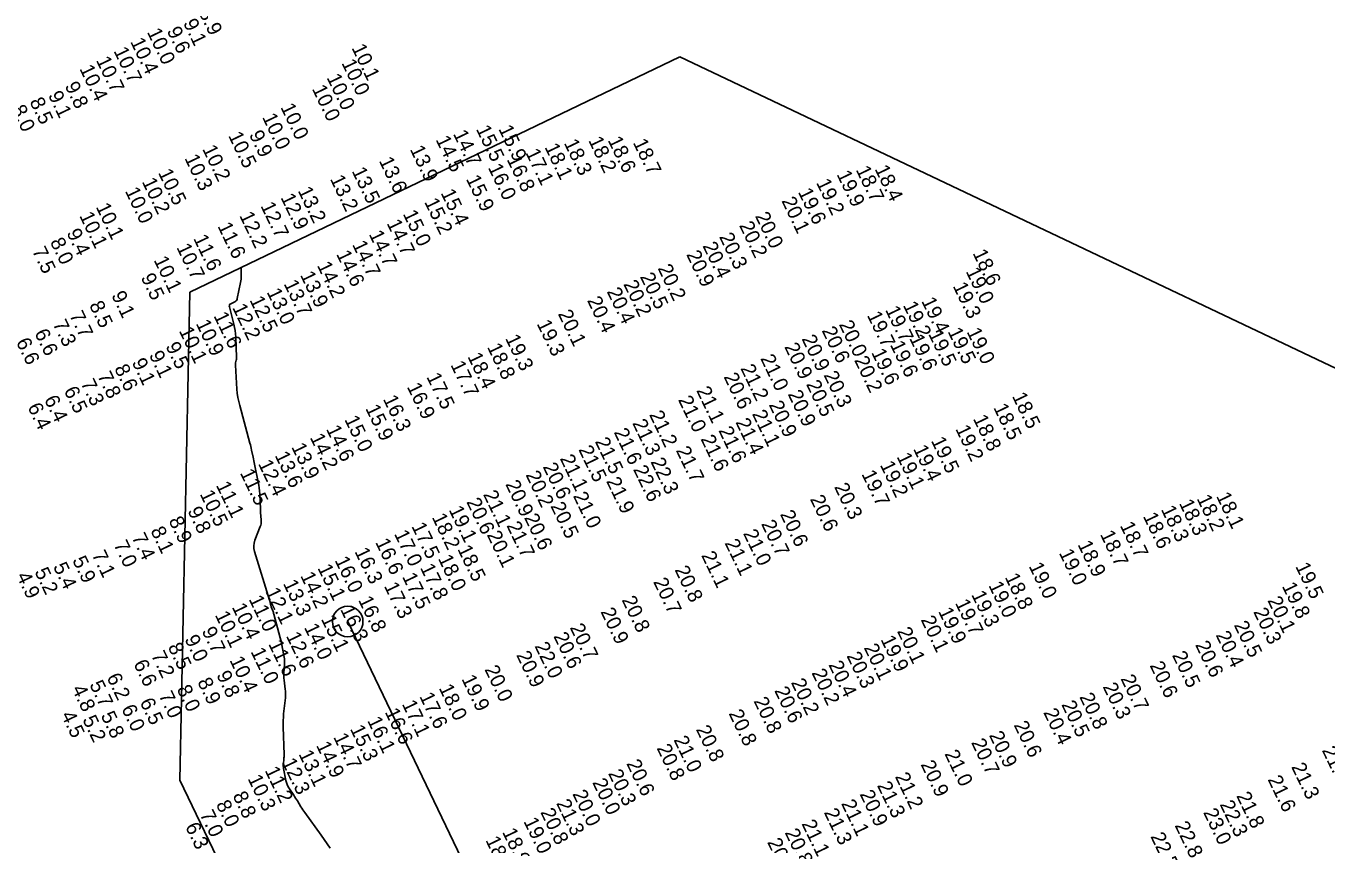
# Model space of a CAD drawing. Extents: x 507575 to 511975, y 1309304 to 1312704.
# Drawn here: x 508170 to 509066, y 1310994 to 1311558 of the extents above; entities that cross this region are included whole.
import ezdxf

# ---------------------------------------------------------------- set-up
doc = ezdxf.new("R2010")
doc.units = 0
for name, color, linetype in [('C-CHAN-CNTR', 7, 'Continuous'), ('C-CHAN-TBAS', 7, 'Continuous'), ('V-CHAN-CNTR-IDEN', 7, 'Continuous'), ('V-TOPO-MAJR', 7, 'Continuous'), ('V-TOPO-SOUN', 7, 'Continuous')]:
    doc.layers.add(name, color=color, linetype=linetype)

msp = doc.modelspace()

# ---------------------------------------------------------------- linework, layer by layer
at = {"layer": 'C-CHAN-CNTR'}
msp.add_line((508990.23, 1309901.57), (508391.7, 1311148.18), dxfattribs=at)
at = {"layer": 'C-CHAN-TBAS'}
for p, q in [((508620.36, 1311537.08), (508283.12, 1311375.16)), ((508620.36, 1311537.08), (509259.42, 1311233.71)), ((508276.04, 1311039.02), (508283.12, 1311375.16)), ((508276.04, 1311039.02), (508487, 1310599.65))]:
    msp.add_line(p, q, dxfattribs=at)
at = {"layer": 'V-CHAN-CNTR-IDEN'}
msp.add_circle((508391.7, 1311148.18), 10.54, dxfattribs=at)
at = {"layer": 'V-TOPO-MAJR'}
msp.add_lwpolyline([(508318.31, 1311392.06), (508318.32, 1311391.23), (508318.39, 1311386.42), (508318.37, 1311385.23), (508318.29, 1311384.03), (508318.15, 1311382.85), (508317.94, 1311381.67), (508315.71, 1311370.73), (508315.49, 1311370.01), (508315.13, 1311369.41), (508314.64, 1311368.9), (508314.01, 1311368.5), (508311.22, 1311367.1), (508310.64, 1311366.7), (508310.28, 1311366.2), (508310.14, 1311365.6), (508310.23, 1311364.89), (508313.33, 1311353.05), (508313.85, 1311350.82), (508314.25, 1311348.56), (508314.52, 1311346.29), (508314.67, 1311344), (508315.17, 1311330.02), (508315.17, 1311329.57), (508315.14, 1311329.12), (508315.08, 1311328.68), (508314.98, 1311328.23), (508314.54, 1311326.48), (508314.45, 1311326.04), (508314.39, 1311325.59), (508314.37, 1311325.15), (508314.38, 1311324.7), (508315.45, 1311308.31), (508315.71, 1311305.44), (508316.11, 1311302.6), (508316.66, 1311299.78), (508317.35, 1311296.98), (508324.43, 1311271.14), (508324.75, 1311269.94), (508325.04, 1311268.72), (508325.32, 1311267.51), (508325.57, 1311266.28), (508326.54, 1311261.38), (508326.78, 1311260.16), (508327.03, 1311258.93), (508327.28, 1311257.71), (508327.53, 1311256.49), (508330.09, 1311244.27), (508330.48, 1311242.23), (508330.78, 1311240.18), (508331, 1311238.12), (508331.13, 1311236.04), (508331.61, 1311225.59), (508331.66, 1311224.58), (508331.71, 1311223.57), (508331.77, 1311222.56), (508331.84, 1311221.55), (508332.11, 1311217.52), (508332.13, 1311216.52), (508332.03, 1311215.54), (508331.83, 1311214.57), (508331.52, 1311213.62), (508327.86, 1311204.18), (508327.3, 1311202.29), (508327.06, 1311200.38), (508327.16, 1311198.46), (508327.59, 1311196.54), (508337.96, 1311162.98), (508338.07, 1311162.6), (508338.17, 1311162.21), (508338.26, 1311161.83), (508338.34, 1311161.44), (508338.63, 1311159.88), (508338.71, 1311159.49), (508338.81, 1311159.11), (508338.92, 1311158.73), (508339.06, 1311158.36), (508340.11, 1311155.6), (508340.32, 1311155.01), (508340.52, 1311154.42), (508340.71, 1311153.82), (508340.88, 1311153.22), (508345.25, 1311137.03), (508345.66, 1311135.45), (508346.03, 1311133.87), (508346.38, 1311132.29), (508346.68, 1311130.69), (508347.96, 1311123.73), (508348.16, 1311122.41), (508348.27, 1311121.09), (508348.29, 1311119.76), (508348.23, 1311118.43), (508347.8, 1311113.1), (508347.73, 1311111.76), (508347.73, 1311110.43), (508347.8, 1311109.1), (508347.94, 1311107.77), (508348.76, 1311101.62), (508348.91, 1311100.15), (508348.97, 1311098.68), (508348.94, 1311097.21), (508348.83, 1311095.74), (508347.62, 1311084.69), (508347.41, 1311082.36), (508347.28, 1311080.02), (508347.23, 1311077.68), (508347.27, 1311075.34), (508347.88, 1311056.69), (508347.9, 1311055.88), (508347.88, 1311055.06), (508347.83, 1311054.25), (508347.76, 1311053.44), (508347.4, 1311050.19), (508347.34, 1311049.38), (508347.34, 1311048.57), (508347.4, 1311047.77), (508347.53, 1311046.97), (508349.15, 1311038.69), (508349.48, 1311037.34), (508349.93, 1311036.05), (508350.51, 1311034.81), (508351.22, 1311033.61), (508354.53, 1311028.59), (508355.18, 1311027.6), (508355.82, 1311026.61), (508356.45, 1311025.61), (508357.07, 1311024.61), (508359.54, 1311020.59), (508360.17, 1311019.59), (508360.82, 1311018.6), (508361.48, 1311017.63), (508362.17, 1311016.67), (508373.5, 1311001.03), (508375.6, 1310998.09), (508377.66, 1310995.12), (508379.68, 1310992.13)], dxfattribs=at)

# ---------------------------------------------------------------- texts
at = {"layer": 'V-TOPO-SOUN'}
for s, p in [('8.9', (508288.92, 1311567.85)), ('9.6', (508266.96, 1311555.2)), ('9.1', (508278.2, 1311560.62)), ('10.4 ', (508241.79, 1311547.67)), ('10.0 ', (508253.31, 1311554.29)), ('10.7 ', (508230.31, 1311541.32)), ('10.1 ', (508394.19, 1311543.41)), ('10.4 ', (508206.81, 1311529.04)), ('10.7 ', (508218.21, 1311534.86)), ('10.0 ', (508387.24, 1311532.97)), ('10.0 ', (508377.03, 1311522.89)), ('9.1', (508185.24, 1311510.88)), ('9.8', (508196.66, 1311517.27)), ('10.0 ', (508366.94, 1311515.2)), ('8.0', (508159.98, 1311501.27)), ('8.5', (508172.44, 1311506.42)), ('10.0 ', (508345.21, 1311502.56)), ('10.0 ', (508332.61, 1311495.68)), ('9.9', (508323.57, 1311483.73)), ('14.7 ', (508464.08, 1311484.19)), ('15.5 ', (508479.88, 1311487.44)), ('15.9 ', (508495.32, 1311487.59)), ('10.5 ', (508309.23, 1311482.98)), ('14.5 ', (508452.11, 1311480.2)), ('18.1 ', (508527.09, 1311475.03)), ('18.3 ', (508540.38, 1311477.92)), ('18.2 ', (508557.23, 1311479.66)), ('18.6 ', (508570.62, 1311479.77)), ('18.7 ', (508587.94, 1311478.11)), ('10.3 ', (508279.12, 1311467.44)), ('10.2 ', (508291.37, 1311473.81)), ('13.9 ', (508434.34, 1311473.56)), ('16.8 ', (508501.02, 1311466.59)), ('17.1 ', (508513.94, 1311471.27)), ('10.5 ', (508260.94, 1311457.42)), ('13.5 ', (508394.3, 1311458.59)), ('13.6 ', (508413.03, 1311465.62)), ('16.0 ', (508488.14, 1311460.91)), ('18.7 ', (508741.42, 1311459.46)), ('18.4 ', (508754.41, 1311459.99)), ('10.2 ', (508249.8, 1311451.24)), ('13.2 ', (508379.34, 1311453.17)), ('15.9 ', (508472.99, 1311453.1)), ('19.2 ', (508714.14, 1311450.53)), ('19.9 ', (508728.19, 1311456.28)), ('10.0 ', (508238.16, 1311444.77)), ('12.9 ', (508345.27, 1311440.41)), ('13.2 ', (508357.15, 1311445.08)), ('15.4 ', (508455.55, 1311443.47)), ('19.6 ', (508701.61, 1311444.14)), ('10.1 ', (508218.08, 1311433.87)), ('12.7 ', (508331.47, 1311434.6)), ('15.2 ', (508444.28, 1311437.25)), ('20.1 ', (508690.27, 1311438.03)), ('10.1 ', (508206.72, 1311427.76)), ('12.2 ', (508316.9, 1311427.88)), ('14.7 ', (508418.35, 1311422.61)), ('15.0 ', (508429.49, 1311429.06)), ('20.2 ', (508661.08, 1311421.15)), ('20.0 ', (508672.02, 1311427.61)), ('9.4', (508197.94, 1311416.03)), ('11.6 ', (508301.87, 1311420.6)), ('14.7 ', (508406.08, 1311415.05)), ('20.3 ', (508647.32, 1311413.29)), ('7.5', (508174.15, 1311403.6)), ('8.0', (508186.53, 1311409.83)), ('10.7 ', (508273.59, 1311405.99)), ('11.6 ', (508285.2, 1311412.16)), ('14.7 ', (508394.6, 1311407.97)), ('20.4 ', (508635.9, 1311407.02)), ('10.1 ', (508257.93, 1311397.28)), ('14.6 ', (508383.64, 1311401.32)), ('20.9 ', (508624.66, 1311401.12)), ('18.6 ', (508821.86, 1311402.01)), ('9.5', (508249.03, 1311385.3)), ('13.9 ', (508358.77, 1311386.91)), ('14.2 ', (508370.4, 1311393.52)), ('20.5 ', (508592.8, 1311385.82)), ('20.2 ', (508604.98, 1311391.6)), ('19.0 ', (508817.12, 1311389.46)), ('13.7 ', (508347.47, 1311380.9)), ('20.2 ', (508581.38, 1311380.67)), ('19.3 ', (508808.2, 1311379.33)), ('9.1', (508228.76, 1311373.05)), ('12.5 ', (508323.93, 1311369.76)), ('13.0 ', (508335.74, 1311375.18)), ('20.4 ', (508556.38, 1311369.44)), ('20.4 ', (508569.94, 1311375.56)), ('19.4 ', (508786.56, 1311369)), ('7.7', (508199.89, 1311359.27)), ('8.5', (508213.49, 1311366.23)), ('11.6 ', (508299.15, 1311358.83)), ('12.2 ', (508312.06, 1311364.48)), ('20.1 ', (508536.27, 1311360.24)), ('19.7 ', (508749.1, 1311359.25)), ('19.7 ', (508761.65, 1311362.97)), ('19.2 ', (508773.91, 1311366.08)), ('7.3', (508188.39, 1311353.34)), ('10.9 ', (508286.95, 1311353.53)), ('19.3 ', (508521.67, 1311353.42)), ('20.0 ', (508729.81, 1311352.96)), ('6.6', (508163.13, 1311340.82)), ('6.6', (508175.79, 1311346.99)), ('10.1 ', (508275.29, 1311348.55)), ('19.3 ', (508499.99, 1311343.33)), ('20.9 ', (508704.11, 1311342.99)), ('20.6 ', (508717.97, 1311348.69)), ('19.6 ', (508778.23, 1311343.38)), ('19.5 ', (508791.3, 1311346.41)), ('19.5 ', (508804.65, 1311348.05)), ('19.0 ', (508817.72, 1311347.91)), ('9.1', (508254.7, 1311331.93)), ('9.5', (508266.09, 1311337.96)), ('18.8 ', (508487.51, 1311337.31)), ('20.9 ', (508692.19, 1311337.52)), ('19.6 ', (508752.07, 1311333.58)), ('19.6 ', (508764.98, 1311338.91)), ('8.6', (508230.78, 1311322.63)), ('9.1', (508242.89, 1311326.84)), ('17.7 ', (508462.31, 1311325.11)), ('18.4 ', (508473.99, 1311330.83)), ('21.2 ', (508661.98, 1311322.69)), ('21.0 ', (508675.67, 1311329.49)), ('20.2 ', (508740.33, 1311328.3)), ('7.8', (508219.16, 1311317.57)), ('17.5 ', (508445.72, 1311316.84)), ('20.6 ', (508650.4, 1311316.86)), ('20.3 ', (508719.26, 1311318.07)), ('6.5', (508196.06, 1311307.39)), ('7.3', (508207.64, 1311312.45)), ('16.9 ', (508432.28, 1311309.99)), ('21.1 ', (508631.58, 1311307.4)), ('20.9 ', (508694.57, 1311304.9)), ('20.5 ', (508707.19, 1311311.75)), ('6.4', (508171.05, 1311296.02)), ('6.4', (508182.48, 1311301.25)), ('16.3 ', (508415.8, 1311301.52)), ('21.0 ', (508619.04, 1311301)), ('20.9 ', (508681.5, 1311297.6)), ('18.5 ', (508848.99, 1311303.48)), ('15.0 ', (508389.26, 1311287.46)), ('15.9 ', (508403.69, 1311295.1)), ('21.2 ', (508599.13, 1311290.79)), ('21.1 ', (508669.97, 1311291.27)), ('18.8 ', (508822.12, 1311288)), ('18.5 ', (508836.12, 1311295.69)), ('14.6 ', (508376.64, 1311280.82)), ('21.6 ', (508574.79, 1311278.65)), ('21.3 ', (508587.54, 1311284.89)), ('21.6 ', (508646.85, 1311279.87)), ('21.4 ', (508658.57, 1311285.54)), ('19.2 ', (508809.99, 1311280.93)), ('14.2 ', (508365.47, 1311275.08)), ('21.5 ', (508561.77, 1311272.28)), ('21.6 ', (508634.54, 1311274.05)), ('19.5 ', (508793.19, 1311272.81)), ('13.6 ', (508341.26, 1311262.75)), ('13.9 ', (508352.68, 1311268.59)), ('21.1 ', (508537.66, 1311260.51)), ('21.5 ', (508550.43, 1311266.74)), ('21.7 ', (508617.51, 1311266.2)), ('19.1 ', (508769.53, 1311261.82)), ('19.4 ', (508780.91, 1311267.2)), ('12.4 ', (508329.82, 1311256.98)), ('20.6 ', (508525.84, 1311254.9)), ('22.6 ', (508588.07, 1311253.12)), ('22.3 ', (508600.07, 1311258.34)), ('19.2 ', (508758.06, 1311256.13)), ('11.1 ', (508300.82, 1311242.09)), ('11.5 ', (508317.31, 1311250.66)), ('20.9 ', (508500.09, 1311242.85)), ('20.2 ', (508514.03, 1311249.33)), ('21.9 ', (508569.54, 1311244.96)), ('19.7 ', (508745.34, 1311249.85)), ('10.5 ', (508289.65, 1311236.11)), ('21.1 ', (508484.77, 1311235.86)), ('21.0 ', (508546.7, 1311234.8)), ('20.6 ', (508709.87, 1311232.68)), ('20.3 ', (508726.54, 1311240.97)), ('18.1 ', (508989.53, 1311234.66)), ('9.8', (508281.24, 1311224.56)), ('19.1 ', (508461.12, 1311225.25)), ('20.6 ', (508473.27, 1311230.66)), ('20.5 ', (508531.15, 1311227.86)), ('18.3 ', (508951.55, 1311225.5)), ('18.3 ', (508963.97, 1311229.79)), ('18.2 ', (508976.16, 1311232.97)), ('8.9', (508268.2, 1311217.82)), ('18.2 ', (508449.48, 1311220.12)), ('20.6 ', (508513.01, 1311219.84)), ('20.7 ', (508676.26, 1311215.49)), ('20.6 ', (508689.23, 1311222.18)), ('18.6 ', (508939.14, 1311220.75)), ('7.4', (508242.74, 1311206.3)), ('8.1', (508255.73, 1311210.86)), ('17.0 ', (508423.5, 1311208.63)), ('17.5 ', (508435.42, 1311213.89)), ('20.1 ', (508487.34, 1311208.01)), ('21.7 ', (508500.87, 1311214.39)), ('21.0 ', (508663.8, 1311209)), ('18.7 ', (508909.6, 1311208.35)), ('18.7 ', (508923.33, 1311214.33)), ('7.0', (508230.32, 1311201.29)), ('16.6 ', (508410.51, 1311202.86)), ('18.5 ', (508467.06, 1311198.23)), ('21.1 ', (508651.11, 1311202.35)), ('18.9 ', (508894.15, 1311201.33)), ('5.9', (508201.85, 1311190.49)), ('7.1', (508215.33, 1311194.34)), ('16.0 ', (508382.56, 1311190.44)), ('16.3 ', (508396.21, 1311196.53)), ('18.0 ', (508453.74, 1311191.61)), ('21.1 ', (508634.99, 1311193.89)), ('19.0 ', (508881.29, 1311195.54)), ('5.2', (508175.88, 1311182.57)), ('5.4', (508188.62, 1311186.16)), ('14.2 ', (508358.9, 1311179.77)), ('15.1 ', (508370.74, 1311185.12)), ('17.8 ', (508441.35, 1311185.38)), ('20.8 ', (508616.65, 1311183.92)), ('19.0 ', (508860.52, 1311186.36)), ('19.5 ', (509044.09, 1311186.26)), ('4.9', (508163.4, 1311179.66)), ('13.3 ', (508347.01, 1311174.39)), ('17.3 ', (508416.53, 1311172.67)), ('17.5 ', (508429.02, 1311179.13)), ('20.7 ', (508601.93, 1311175.61)), ('19.0 ', (508832.75, 1311173.19)), ('18.8 ', (508844, 1311178.85)), ('19.8 ', (509034.83, 1311172.67)), ('11.0 ', (508323.38, 1311163.66)), ('12.1 ', (508334.89, 1311168.89)), ('16.8 ', (508398.74, 1311163.13)), ('20.8 ', (508580.23, 1311163.13)), ('19.3 ', (508820.94, 1311166.8)), ('20.1 ', (509024.87, 1311162.83)), ('10.1 ', (508300.06, 1311152.81)), ('10.4 ', (508311.74, 1311158.23)), ('16.3 ', (508386.41, 1311156.65)), ('20.9 ', (508565.63, 1311155.07)), ('19.9 ', (508798.16, 1311155.28)), ('19.7 ', (508809.78, 1311161.01)), ('20.3 ', (509015.13, 1311154.95)), ('14.0 ', (508361.46, 1311144.23)), ('15.1 ', (508373.16, 1311149.93)), ('20.7 ', (508544.48, 1311144.1)), ('20.1 ', (508786.13, 1311149.52)), ('20.5 ', (509001.74, 1311145.9)), ('9.0', (508279.18, 1311136.25)), ('9.7', (508290.99, 1311141.81)), ('12.6 ', (508349.02, 1311138.39)), ('20.6 ', (508533.22, 1311138.14)), ('19.9 ', (508758.47, 1311135.98)), ('20.1 ', (508769.84, 1311141.59)), ('20.4 ', (508989.25, 1311138.98)), ('7.2', (508256.13, 1311125.06)), ('8.5', (508267.66, 1311130.81)), ('11.0 ', (508324.68, 1311127.56)), ('11.6 ', (508336.85, 1311132.86)), ('20.9 ', (508507.59, 1311125.23)), ('22.0 ', (508520.19, 1311131.42)), ('20.1 ', (508746.93, 1311130.27)), ('20.5 ', (508959.2, 1311125.08)), ('20.6 ', (508975.14, 1311132.18)), ('6.6', (508244, 1311119.2)), ('10.4 ', (508310.16, 1311121.62)), ('20.4 ', (508722.62, 1311118.49)), ('20.3 ', (508735.09, 1311124.6)), ('20.6 ', (508943.78, 1311118.05)), ('6.2', (508225.49, 1311109.85)), ('9.8', (508301.07, 1311111.54)), ('19.9 ', (508469.86, 1311108.83)), ('20.0 ', (508485.73, 1311115.35)), ('20.2 ', (508710.96, 1311112.95)), ('20.7 ', (508923.72, 1311108.94)), ('4.8', (508201.51, 1311101.84)), ('5.7', (508213.65, 1311104.85)), ('8.0', (508273.8, 1311101.76)), ('8.9', (508287.98, 1311106.76)), ('18.0 ', (508454.27, 1311102.44)), ('20.6 ', (508685.31, 1311100.68)), ('20.2 ', (508696.77, 1311106.26)), ('20.3 ', (508911.44, 1311103.4)), ('6.5', (508248.31, 1311092.76)), ('7.0', (508261.37, 1311097.35)), ('17.1 ', (508428.85, 1311091.46)), ('17.6 ', (508440.89, 1311096.77)), ('20.8 ', (508671.04, 1311093.54)), ('20.5 ', (508883, 1311091.05)), ('20.8 ', (508895.37, 1311096.37)), ('4.5', (508194.12, 1311083.81)), ('5.2', (508208.83, 1311080.78)), ('5.8', (508221.47, 1311083.54)), ('6.0', (508235.68, 1311088.23)), ('16.6 ', (508417.07, 1311085.93)), ('20.8 ', (508653.86, 1311084.9)), ('20.4 ', (508870.56, 1311085.69)), ('15.3 ', (508393.11, 1311074.35)), ('16.1 ', (508404.96, 1311080.06)), ('20.8 ', (508631.33, 1311074.03)), ('20.6 ', (508850.19, 1311077.01)), ('14.9 ', (508369.76, 1311062.95)), ('14.7 ', (508381.59, 1311068.72)), ('21.0 ', (508615.97, 1311066.75)), ('20.7 ', (508820.88, 1311064.88)), ('20.9 ', (508833.15, 1311069.96)), ('13.1 ', (508357.66, 1311057.07)), ('20.8 ', (508604.28, 1311061.09)), ('21.0 ', (508802.52, 1311057.09)), ('21.5 ', (509062.39, 1311059.58)), ('11.2 ', (508334.39, 1311045.75)), ('12.3 ', (508346.15, 1311051.48)), ('20.6 ', (508583.43, 1311050.46)), ('20.9 ', (508786.06, 1311049.86)), ('21.3 ', (509041.27, 1311048.21)), ('10.3 ', (508322.63, 1311040.09)), ('20.0 ', (508559.94, 1311037.44)), ('20.3 ', (508570.86, 1311043.67)), ('21.2 ', (508768.39, 1311041.46)), ('21.6 ', (509025.03, 1311039.48)), ('8.8', (508312.29, 1311028.37)), ('20.0 ', (508546.29, 1311029.54)), ('20.9 ', (508744.08, 1311029.44)), ('21.3 ', (508756.05, 1311035.38)), ('21.8 ', (509003.44, 1311028.19)), ('8.0', (508300.79, 1311022.37)), ('21.3 ', (508535.14, 1311023.08)), ('21.1 ', (508731.33, 1311022.89)), ('22.3 ', (508992, 1311022.36)), ('7.0', (508289.72, 1311015.48)), ('19.0 ', (508512.58, 1311010.66)), ('20.8 ', (508524.21, 1311016.93)), ('21.1 ', (508704.05, 1311009.02)), ('21.3 ', (508719.44, 1311016.81)), ('23.0 ', (508980.63, 1311016.84)), ('6.3', (508279.62, 1311007.02)), ('18.6 ', (508497.91, 1311003.29)), ('20.8 ', (508692.49, 1311002.87)), ('22.5 ', (508944.31, 1311000.22)), ('22.8 ', (508961, 1311007.83)), ('18.3 ', (508486.38, 1310997.7)), ('20.8 ', (508680.43, 1310996.28))]:
    msp.add_text(s, height=9.996, rotation=295.6464, dxfattribs=at).set_placement(p)

doc.saveas('drawing.dxf')
